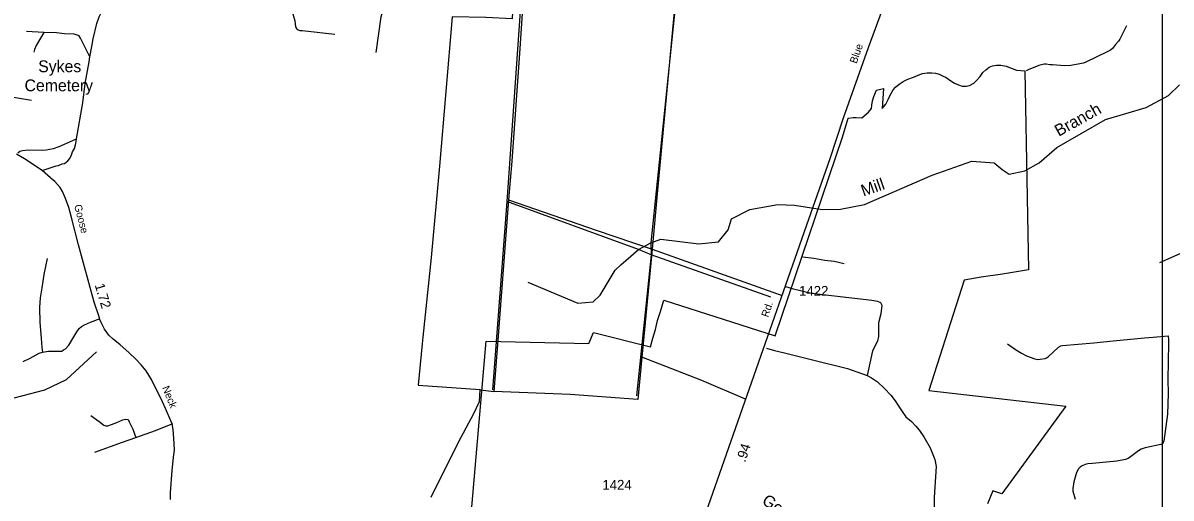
# Model space of a CAD drawing. Extents: x 2225501 to 2309677, y 165449 to 227696.
# Drawn here: x 2251795 to 2266364, y 212881 to 218912 of the extents above; entities that cross this region are included whole.
import ezdxf

# ---------------------------------------------------------------- set-up
doc = ezdxf.new("R2010")
doc.units = 0
for name, color, linetype in [('E_RDY_CMT_EOP', 7, 'Continuous'), ('Exist Vegetation Text', 7, 'Continuous'), ('MARK ENDS WORD SYMBOL CELL', 7, 'Continuous'), ('Old_Level_3', 7, 'Continuous'), ('Old_Level_33', 7, 'Continuous'), ('P_HYD_Endwall_838_01_48_Dia_Single_CELL', 7, 'Continuous'), ('P_HYD_Pipe_Pipe_Removal', 7, 'Continuous'), ('P_HYD_RipRap_Pad_876_02_36in_Outlet_With_Ditch-Top_CELL', 7, 'Continuous'), ('P_RDY_Dimension_Text', 7, 'Continuous'), ('Prop Support', 7, 'Continuous'), ('Scratch_Level_1', 7, 'Continuous'), ('Typical Terminator CELL', 7, 'Continuous')]:
    doc.layers.add(name, color=color, linetype=linetype)

msp = doc.modelspace()

# ---------------------------------------------------------------- linework, layer by layer
at = {"layer": 'Old_Level_3'}
for p, q in [((2260291, 221543), (2259848, 216791)), ((2252061, 218789), (2251841, 218805)), ((2257958, 216666), (2257867, 215498)), ((2257958, 216666), (2259070, 216283)), ((2259848, 216791), (2259778, 216039)), ((2259070, 216283), (2259778, 216039)), ((2259778, 216039), (2259664, 214844)), ((2259778, 216039), (2261430, 215454)), ((2266514, 215997), (2266219, 215866)), ((2257867, 215498), (2257820, 214885)), ((2261470, 215568), (2261557, 215543)), ((2257820, 214885), (2257770, 214233)), ((2259664, 214844), (2259648, 214671)), ((2257597, 214257), (2257634, 214252)), ((2257634, 214252), (2257770, 214233))]:
    msp.add_line(p, q, dxfattribs=at)
for points in [[(2258253, 222403), (2258221, 221754), (2258188, 221195), (2258132, 220579), (2258091, 219939), (2258059, 219501), (2258051, 219307), (2258035, 219217), (2258010, 219144), (2258002, 218966), (2257670, 218982), (2257241, 218990), (2257079, 217094), (2256973, 215935), (2256868, 214921), (2256860, 214840)], [(2258311, 222319), (2258261, 221709), (2258257, 221469), (2258278, 221307), (2258273, 221183), (2258098, 218590), (2257998, 217156), (2257958, 216666)], [(2254406, 219552), (2254528, 219541), (2254658, 219518), (2254746, 219499), (2254800, 219473), (2254865, 219436), (2254901, 219418), (2254983, 219363), (2255102, 219248), (2255156, 219178), (2255191, 219129), (2255244, 218939), (2255253, 218861), (2255267, 218841), (2255287, 218823), (2255307, 218818), (2255337, 218818), (2255753, 218769)], [(2252643, 218484), (2252670, 218612), (2252685, 218712), (2252732, 218907), (2252763, 218989), (2252786, 219039), (2252822, 219091), (2252870, 219126), (2252904, 219142), (2252956, 219156), (2253031, 219161), (2253346, 219117)], [(2265799, 218874), (2265715, 218708), (2265698, 218680), (2265660, 218640), (2265621, 218589), (2265595, 218567), (2265563, 218549), (2265275, 218411), (2265251, 218403), (2265207, 218392), (2265094, 218373), (2265014, 218366), (2264861, 218379)], [(2252061, 218789), (2251962, 218628), (2251943, 218576), (2251933, 218542)], [(2252643, 218484), (2252525, 218719), (2252511, 218739), (2252495, 218753), (2252443, 218770), (2252321, 218775), (2252219, 218786), (2252061, 218789)], [(2252472, 217439), (2252554, 217899), (2252586, 218142), (2252636, 218420), (2252643, 218484)], [(2264861, 218379), (2264825, 218382), (2264779, 218389), (2264753, 218389), (2264722, 218382), (2264688, 218372), (2264552, 218318), (2264524, 218306)], [(2251731, 217265), (2251757, 217283), (2251787, 217293), (2251859, 217300), (2252045, 217297), (2252091, 217302), (2252183, 217319), (2252255, 217343), (2252320, 217372), (2252358, 217392), (2252472, 217439)], [(2252039, 217041), (2252215, 217097), (2252245, 217101), (2252292, 217122), (2252320, 217128), (2252366, 217162), (2252388, 217192), (2252409, 217236), (2252423, 217277), (2252449, 217319), (2252464, 217381), (2252472, 217439)], [(2252101, 215922), (2252061, 215717), (2252035, 215548), (2252012, 215423), (2252003, 215298), (2252008, 215111), (2252026, 214911), (2252035, 214791), (2252041, 214734)], [(2262214, 215852), (2262088, 215884), (2261969, 215898), (2261832, 215922), (2261691, 215938)], [(2261557, 215543), (2261800, 215480), (2262566, 215394), (2262638, 215381), (2262675, 215363), (2262693, 215331), (2262682, 215221), (2262653, 215103), (2262652, 214931), (2262639, 214871), (2262576, 214748), (2262506, 214436)], [(2252041, 214734), (2252119, 214746), (2252173, 214745), (2252253, 214745), (2252288, 214747), (2252311, 214761), (2252335, 214776), (2252377, 214823), (2252440, 214928), (2252478, 214990), (2252506, 215032), (2252538, 215057), (2252575, 215081), (2252653, 215115), (2252774, 215160)], [(2266328, 214942), (2266333, 214888), (2266333, 214844), (2266324, 214384), (2266326, 214208), (2266320, 213944), (2266271, 213602), (2266265, 213586), (2266258, 213574), (2266235, 213560), (2266035, 213518), (2265987, 213501), (2265951, 213479), (2265851, 213403), (2265821, 213383), (2265787, 213370), (2265677, 213349), (2265369, 213321), (2265309, 213313), (2265273, 213305), (2265235, 213290), (2265209, 213273), (2265189, 213251), (2265165, 213207), (2265129, 213085), (2265117, 213002), (2265118, 212969), (2265149, 212865)], [(2265184, 214833), (2265383, 214851), (2265631, 214878), (2266028, 214916), (2266136, 214924), (2266328, 214942)], [(2256860, 214840), (2256811, 214313), (2257597, 214257)], [(2261230, 214783), (2261330, 214754), (2261460, 214725), (2261797, 214638), (2262257, 214524), (2262506, 214436)], [(2264289, 214839), (2264390, 214766), (2264465, 214719), (2264529, 214688), (2264637, 214647), (2264668, 214641), (2264704, 214642), (2264767, 214653), (2264783, 214661), (2264803, 214675), (2264934, 214796), (2264967, 214811), (2264986, 214816), (2265184, 214833)], [(2251799, 214613), (2251886, 214658), (2252001, 214718), (2252041, 214734)], [(2259648, 214671), (2259596, 214130), (2258739, 214196), (2257770, 214233)], [(2260962, 214138), (2260408, 214374), (2259648, 214671)], [(2262506, 214436), (2262564, 214405), (2262639, 214355), (2262727, 214272), (2262810, 214185), (2262863, 214115), (2262903, 214055), (2262950, 213980), (2262998, 213910), (2263069, 213853), (2263127, 213793), (2263172, 213740), (2263226, 213658), (2263309, 213517), (2263367, 213371), (2263385, 213282), (2263356, 212889), (2263351, 212306)], [(2256973, 212891), (2257322, 213588), (2257516, 213953), (2257589, 214107), (2257597, 214257)], [(2252655, 213928), (2252763, 213853), (2252823, 213807), (2252847, 213797), (2252870, 213797), (2252917, 213816), (2252987, 213839), (2253061, 213872), (2253094, 213881), (2253131, 213877), (2253141, 213849), (2253187, 213755), (2253225, 213648)], [(2253225, 213648), (2253477, 213737), (2253697, 213825)], [(2252707, 213461), (2253057, 213592), (2253225, 213648)]]:
    msp.add_lwpolyline(points, dxfattribs=at)
at = {"layer": 'Old_Level_33'}
for points in [[(2262890, 219654), (2262869, 219562), (2262857, 219519), (2262522, 218596), (2262202, 217703), (2262033, 217188), (2261762, 216419), (2260197, 211949), (2260121, 211814), (2260069, 211762), (2259986, 211722), (2259866, 211664), (2259693, 211606), (2259466, 211514), (2259333, 211475), (2259261, 211462), (2259169, 211468), (2258985, 211468), (2258808, 211471), (2258716, 211462), (2258607, 211410)], [(2253668, 212862), (2253668, 212949), (2253689, 213232), (2253696, 213309), (2253707, 213398), (2253716, 213489), (2253714, 213579), (2253701, 213751), (2253687, 213821), (2253683, 213831), (2253603, 214017), (2253565, 214101), (2253534, 214164), (2253495, 214244), (2253426, 214387), (2253357, 214497), (2253295, 214571), (2253230, 214640), (2253137, 214727), (2253028, 214827), (2252940, 214899), (2252884, 214948), (2252830, 215023), (2252787, 215110), (2252770, 215148), (2252758, 215192), (2252700, 215368), (2252499, 216095), (2252410, 216441), (2252377, 216568), (2252334, 216684), (2252297, 216772), (2252265, 216824), (2252200, 216899), (2252154, 216936), (2252146, 216946), (2252039, 217041), (2251814, 217186), (2251712, 217245)]]:
    msp.add_lwpolyline(points, dxfattribs=at)
at = {"layer": 'P_HYD_Endwall_838_01_48_Dia_Single_CELL'}
for points in [[(2262714, 218078), (2262699, 217827), (2262743, 217882), (2262776, 217941), (2262800, 217996), (2262839, 218065), (2262869, 218098), (2262914, 218134), (2262965, 218167), (2263024, 218197), (2263094, 218226), (2263155, 218249), (2263212, 218272), (2263271, 218277), (2263329, 218280), (2263376, 218273), (2263422, 218261), (2263463, 218242), (2263509, 218218), (2263558, 218185), (2263615, 218149), (2263666, 218125), (2263714, 218109), (2263766, 218109), (2263806, 218120), (2263860, 218148), (2263896, 218180), (2263940, 218234), (2263977, 218283), (2264015, 218319), (2264058, 218350), (2264100, 218369), (2264149, 218377), (2264204, 218377), (2264270, 218362), (2264348, 218336), (2264405, 218312), (2264507, 218306), (2264555, 215776), (2264226, 215725), (2263955, 215684), (2263739, 215646), (2263291, 214244), (2265029, 214046), (2264218, 212935), (2264103, 212972), (2264033, 212808)], [(2257467, 212472), (2257673, 214871), (2258974, 214841), (2259036, 214984), (2259758, 214799), (2259790, 214912), (2259821, 215021), (2259849, 215135), (2259884, 215251), (2259929, 215394), (2261342, 214940), (2262196, 217462), (2262266, 217702), (2262329, 217713), (2262370, 217714), (2262440, 217707), (2262526, 217780), (2262561, 217825), (2262568, 217870), (2262575, 217925), (2262594, 217977), (2262626, 218057), (2262714, 218078)]]:
    msp.add_lwpolyline(points, dxfattribs=at)
at = {"layer": 'P_HYD_Pipe_Pipe_Removal'}
msp.add_lwpolyline([(2243856, 191238), (2266254, 191238), (2266254, 223234), (2243856, 223234)], close=True, dxfattribs=at)
at = {"layer": 'P_HYD_RipRap_Pad_876_02_36in_Outlet_With_Ditch-Top_CELL'}
for points in [[(2262714, 218078), (2262699, 217827), (2262743, 217882), (2262776, 217941), (2262800, 217996), (2262839, 218065), (2262869, 218098), (2262914, 218134), (2262965, 218167), (2263024, 218197), (2263094, 218226), (2263155, 218249), (2263212, 218272), (2263271, 218277), (2263329, 218280), (2263376, 218273), (2263422, 218261), (2263463, 218242), (2263509, 218218), (2263558, 218185), (2263615, 218149), (2263666, 218125), (2263714, 218109), (2263766, 218109), (2263806, 218120), (2263860, 218148), (2263896, 218180), (2263940, 218234), (2263977, 218283), (2264015, 218319), (2264058, 218350), (2264100, 218369), (2264149, 218377), (2264204, 218377), (2264270, 218362), (2264348, 218336), (2264405, 218312), (2264507, 218306), (2264555, 215776), (2264226, 215725), (2263955, 215684), (2263739, 215646), (2263291, 214244), (2265029, 214046), (2264218, 212935), (2264103, 212972), (2264033, 212808)], [(2257467, 212472), (2257673, 214871), (2258974, 214841), (2259036, 214984), (2259758, 214799), (2259790, 214912), (2259821, 215021), (2259849, 215135), (2259884, 215251), (2259929, 215394), (2261342, 214940), (2262196, 217462), (2262266, 217702), (2262329, 217713), (2262370, 217714), (2262440, 217707), (2262526, 217780), (2262561, 217825), (2262568, 217870), (2262575, 217925), (2262594, 217977), (2262626, 218057), (2262714, 218078)]]:
    msp.add_lwpolyline(points, dxfattribs=at)
at = {"layer": 'Prop Support'}
for p, q in [((2260104, 219412), (2259764, 216119)), ((2257936, 216647), (2257755, 214253)), ((2259607, 216034), (2257936, 216647)), ((2259764, 216119), (2259765, 215968)), ((2259765, 215968), (2259580, 214178)), ((2259765, 215968), (2259607, 216034)), ((2261286, 215430), (2259765, 215968))]:
    msp.add_line(p, q, dxfattribs=at)
for points in [[(2258306, 222271), (2258238, 221413), (2258257, 221239), (2257936, 216647)], [(2251903, 217929), (2251261, 218033), (2250838, 218270)]]:
    msp.add_lwpolyline(points, dxfattribs=at)
at = {"layer": 'Typical Terminator CELL'}
msp.add_line((2259607, 216034), (2259764, 216119), dxfattribs=at)
for points in [[(2256279, 218539), (2256342, 218990), (2256456, 219392), (2256751, 219960), (2256880, 220443), (2256846, 221585), (2256819, 221776), (2256583, 222207)], [(2264222, 217051), (2264308, 216991), (2264507, 217033), (2264690, 217135), (2264913, 217331), (2265534, 217686), (2266049, 217840), (2266331, 217992), (2266471, 218127)], [(2259764, 216119), (2259889, 216169), (2260372, 216107), (2260622, 216135), (2260746, 216284), (2260786, 216427), (2261018, 216544), (2261376, 216606), (2261584, 216599), (2261935, 216546), (2262168, 216548), (2262476, 216607), (2263331, 216981), (2263837, 217158), (2264121, 217136), (2264222, 217051)], [(2258202, 215621), (2258837, 215353), (2259029, 215372), (2259120, 215456), (2259309, 215774), (2259383, 215841), (2259607, 216034)], [(2250466, 211495), (2250638, 211528), (2250870, 211707), (2251019, 211875), (2251092, 212067), (2251145, 212824), (2251370, 213744), (2251535, 214020), (2251683, 214155), (2252074, 214255), (2252348, 214384), (2252728, 214738)]]:
    msp.add_lwpolyline(points, dxfattribs=at)

# ---------------------------------------------------------------- texts
at = {"layer": 'E_RDY_CMT_EOP'}
for s, p in [('1422', (2261644, 215448)), ('1424', (2259148, 212986))]:
    msp.add_text(s, height=125, dxfattribs=at).set_placement(p)
at = {"layer": 'Exist Vegetation Text'}
for s, p in [('Sykes', (2251988, 218287)), ('Cemetery', (2251815, 218045))]:
    msp.add_text(s, height=150, dxfattribs=at).set_placement(p)
at = {"layer": 'MARK ENDS WORD SYMBOL CELL'}
for s, rotation, p in [('Blue', 70.7391, (2262373, 218389)), ('Goose', 284.5418, (2252443, 216595)), ('Rd.', 71.1738, (2261251, 215169)), ('Neck', 291.7318, (2253559, 214282))]:
    msp.add_text(s, height=95, rotation=rotation, dxfattribs=at).set_placement(p)
at = {"layer": 'P_RDY_Dimension_Text'}
for s, rotation, p in [('1.72', 286.5497, (2252704, 215586)), ('.94', 72.0484, (2260960, 213327))]:
    msp.add_text(s, height=125, rotation=rotation, dxfattribs=at).set_placement(p)
at = {"layer": 'Scratch_Level_1'}
for s, rotation, p in [('Branch', 29.1202, (2264939, 217466)), ('Mill', 19.2864, (2262460, 216707)), ('George', 326.6254, (2261161, 212816))]:
    msp.add_text(s, height=150, rotation=rotation, dxfattribs=at).set_placement(p)

doc.saveas('drawing.dxf')
